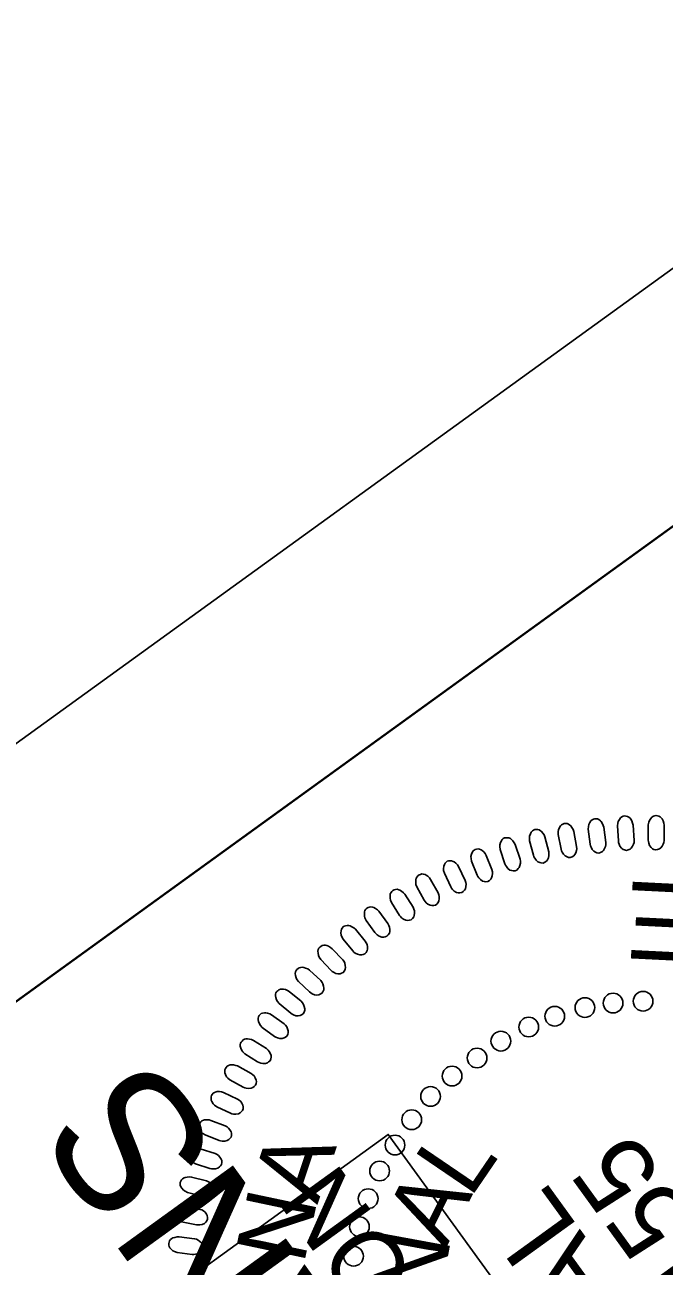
# Model space of a CAD drawing. Extents: x 474248 to 476123, y 501895 to 503900.
# Drawn here: x 474338.6 to 474390.5, y 503280.5 to 503381.5 of the extents above; entities that cross this region are included whole.
import ezdxf

# ---------------------------------------------------------------- set-up
doc = ezdxf.new("R2010")
doc.units = 0
for name, color, linetype in [('Sheet PE Seal Cell', 7, 'Continuous'), ('Sheet Plan CELL', 7, 'Continuous'), ('Sheet Plot Border Outside CELL', 7, 'Continuous'), ('Sheet Sticker Incomplete CELL', 7, 'Continuous')]:
    doc.layers.add(name, color=color, linetype=linetype)

msp = doc.modelspace()

# ---------------------------------------------------------------- linework, layer by layer
at = {"layer": 'Sheet PE Seal Cell'}
for points in [[(474382.16, 503314.41), (474381.94, 503315.62), (474381.93, 503315.84), (474381.96, 503315.99), (474382.04, 503316.17), (474382.11, 503316.3), (474382.21, 503316.4), (474382.3, 503316.46), (474382.41, 503316.5), (474382.52, 503316.5), (474382.65, 503316.49), (474382.76, 503316.45), (474382.88, 503316.37), (474382.96, 503316.31), (474383.05, 503316.17), (474383.14, 503316.01), (474383.19, 503315.85), (474383.43, 503314.62), (474383.44, 503314.45), (474383.42, 503314.3), (474383.37, 503314.13), (474383.28, 503313.97), (474383.2, 503313.88), (474383.06, 503313.79), (474382.91, 503313.74), (474382.76, 503313.75), (474382.65, 503313.78), (474382.5, 503313.86), (474382.36, 503314), (474382.26, 503314.16), (474382.2, 503314.29)], [(474384.52, 503314.82), (474384.37, 503316.04), (474384.38, 503316.26), (474384.41, 503316.41), (474384.5, 503316.59), (474384.59, 503316.71), (474384.69, 503316.8), (474384.79, 503316.85), (474384.9, 503316.89), (474385.01, 503316.88), (474385.13, 503316.87), (474385.24, 503316.82), (474385.36, 503316.73), (474385.43, 503316.66), (474385.51, 503316.52), (474385.59, 503316.35), (474385.64, 503316.2), (474385.8, 503314.95), (474385.8, 503314.78), (474385.77, 503314.63), (474385.7, 503314.47), (474385.61, 503314.31), (474385.52, 503314.22), (474385.37, 503314.14), (474385.23, 503314.1), (474385.07, 503314.13), (474384.96, 503314.16), (474384.82, 503314.25), (474384.69, 503314.4), (474384.6, 503314.57), (474384.55, 503314.69)], [(474386.82, 503315.08), (474386.74, 503316.3), (474386.77, 503316.53), (474386.81, 503316.67), (474386.91, 503316.84), (474387, 503316.96), (474387.11, 503317.05), (474387.21, 503317.09), (474387.32, 503317.12), (474387.43, 503317.11), (474387.55, 503317.08), (474387.66, 503317.03), (474387.77, 503316.94), (474387.84, 503316.86), (474387.91, 503316.71), (474387.98, 503316.54), (474388.02, 503316.38), (474388.1, 503315.13), (474388.09, 503314.96), (474388.05, 503314.82), (474387.97, 503314.65), (474387.87, 503314.5), (474387.78, 503314.42), (474387.62, 503314.35), (474387.48, 503314.32), (474387.32, 503314.35), (474387.22, 503314.39), (474387.08, 503314.49), (474386.95, 503314.65), (474386.88, 503314.82), (474386.84, 503314.95)], [(474389.25, 503315.16), (474389.25, 503316.39), (474389.29, 503316.61), (474389.34, 503316.75), (474389.45, 503316.91), (474389.55, 503317.02), (474389.66, 503317.1), (474389.77, 503317.14), (474389.88, 503317.16), (474389.99, 503317.14), (474390.11, 503317.11), (474390.21, 503317.05), (474390.32, 503316.95), (474390.38, 503316.87), (474390.45, 503316.72), (474390.5, 503316.54), (474390.53, 503316.38), (474390.53, 503315.13), (474390.51, 503314.96), (474390.46, 503314.82), (474390.37, 503314.66), (474390.26, 503314.52), (474390.16, 503314.44), (474390.01, 503314.38), (474389.86, 503314.36), (474389.71, 503314.4), (474389.6, 503314.45), (474389.48, 503314.55), (474389.36, 503314.72), (474389.29, 503314.9), (474389.26, 503315.03)], [(474377.59, 503313.23), (474377.22, 503314.4), (474377.19, 503314.62), (474377.19, 503314.77), (474377.25, 503314.96), (474377.31, 503315.1), (474377.39, 503315.21), (474377.47, 503315.28), (474377.58, 503315.33), (474377.69, 503315.34), (474377.81, 503315.35), (474377.93, 503315.33), (474378.06, 503315.27), (474378.14, 503315.21), (474378.25, 503315.09), (474378.36, 503314.93), (474378.43, 503314.79), (474378.83, 503313.6), (474378.86, 503313.43), (474378.86, 503313.28), (474378.82, 503313.1), (474378.76, 503312.93), (474378.69, 503312.83), (474378.56, 503312.72), (474378.42, 503312.66), (474378.27, 503312.65), (474378.15, 503312.67), (474378, 503312.72), (474377.84, 503312.85), (474377.72, 503313), (474377.65, 503313.11)], [(474379.91, 503313.92), (474379.61, 503315.1), (474379.59, 503315.33), (474379.6, 503315.47), (474379.67, 503315.67), (474379.74, 503315.8), (474379.83, 503315.9), (474379.92, 503315.97), (474380.02, 503316.01), (474380.14, 503316.02), (474380.26, 503316.02), (474380.38, 503315.99), (474380.5, 503315.92), (474380.58, 503315.86), (474380.68, 503315.73), (474380.78, 503315.57), (474380.84, 503315.42), (474381.16, 503314.2), (474381.18, 503314.03), (474381.17, 503313.89), (474381.13, 503313.71), (474381.05, 503313.55), (474380.98, 503313.45), (474380.84, 503313.35), (474380.7, 503313.29), (474380.54, 503313.3), (474380.43, 503313.32), (474380.28, 503313.38), (474380.13, 503313.52), (474380.02, 503313.68), (474379.96, 503313.79)], [(474375.34, 503312.3), (474374.89, 503313.45), (474374.85, 503313.66), (474374.84, 503313.81), (474374.89, 503314.01), (474374.94, 503314.15), (474375.01, 503314.27), (474375.09, 503314.34), (474375.19, 503314.4), (474375.3, 503314.42), (474375.43, 503314.44), (474375.54, 503314.42), (474375.68, 503314.37), (474375.76, 503314.31), (474375.88, 503314.2), (474376, 503314.05), (474376.08, 503313.91), (474376.55, 503312.75), (474376.59, 503312.58), (474376.6, 503312.44), (474376.57, 503312.25), (474376.52, 503312.08), (474376.46, 503311.97), (474376.34, 503311.86), (474376.2, 503311.79), (474376.05, 503311.77), (474375.93, 503311.78), (474375.78, 503311.82), (474375.61, 503311.94), (474375.48, 503312.08), (474375.4, 503312.19)], [(474373.2, 503311.35), (474372.68, 503312.46), (474372.62, 503312.67), (474372.6, 503312.82), (474372.63, 503313.02), (474372.68, 503313.16), (474372.74, 503313.28), (474372.82, 503313.36), (474372.92, 503313.43), (474373.02, 503313.46), (474373.15, 503313.48), (474373.27, 503313.47), (474373.4, 503313.42), (474373.49, 503313.38), (474373.62, 503313.27), (474373.75, 503313.13), (474373.83, 503313), (474374.37, 503311.86), (474374.42, 503311.7), (474374.44, 503311.56), (474374.43, 503311.37), (474374.39, 503311.2), (474374.33, 503311.09), (474374.22, 503310.97), (474374.09, 503310.88), (474373.94, 503310.86), (474373.82, 503310.86), (474373.66, 503310.89), (474373.48, 503311), (474373.35, 503311.13), (474373.27, 503311.24)], [(474371.03, 503310.27), (474370.44, 503311.34), (474370.37, 503311.55), (474370.35, 503311.7), (474370.36, 503311.91), (474370.4, 503312.05), (474370.46, 503312.17), (474370.53, 503312.26), (474370.62, 503312.33), (474370.73, 503312.36), (474370.85, 503312.4), (474370.97, 503312.39), (474371.11, 503312.36), (474371.2, 503312.31), (474371.33, 503312.22), (474371.47, 503312.09), (474371.56, 503311.96), (474372.17, 503310.86), (474372.23, 503310.7), (474372.26, 503310.56), (474372.26, 503310.37), (474372.23, 503310.2), (474372.18, 503310.08), (474372.07, 503309.95), (474371.95, 503309.86), (474371.8, 503309.83), (474371.68, 503309.82), (474371.52, 503309.85), (474371.34, 503309.94), (474371.19, 503310.06), (474371.11, 503310.16)], [(474369.04, 503309.03), (474368.38, 503310.07), (474368.3, 503310.27), (474368.27, 503310.42), (474368.27, 503310.62), (474368.29, 503310.77), (474368.35, 503310.89), (474368.41, 503310.98), (474368.5, 503311.06), (474368.6, 503311.1), (474368.72, 503311.14), (474368.84, 503311.15), (474368.98, 503311.12), (474369.07, 503311.08), (474369.21, 503310.99), (474369.36, 503310.87), (474369.46, 503310.75), (474370.14, 503309.69), (474370.21, 503309.54), (474370.25, 503309.39), (474370.26, 503309.21), (474370.24, 503309.03), (474370.2, 503308.91), (474370.1, 503308.78), (474369.98, 503308.68), (474369.83, 503308.64), (474369.72, 503308.62), (474369.56, 503308.64), (474369.37, 503308.72), (474369.21, 503308.84), (474369.12, 503308.93)], [(474367.04, 503307.63), (474366.32, 503308.62), (474366.22, 503308.82), (474366.18, 503308.96), (474366.18, 503309.17), (474366.19, 503309.31), (474366.23, 503309.44), (474366.3, 503309.54), (474366.37, 503309.62), (474366.48, 503309.67), (474366.59, 503309.71), (474366.71, 503309.73), (474366.85, 503309.71), (474366.95, 503309.68), (474367.09, 503309.6), (474367.25, 503309.49), (474367.36, 503309.37), (474368.1, 503308.36), (474368.18, 503308.21), (474368.23, 503308.07), (474368.25, 503307.88), (474368.24, 503307.71), (474368.21, 503307.58), (474368.11, 503307.44), (474368, 503307.34), (474367.86, 503307.28), (474367.75, 503307.26), (474367.59, 503307.27), (474367.39, 503307.34), (474367.23, 503307.44), (474367.13, 503307.53)], [(474365.24, 503306.14), (474364.46, 503307.09), (474364.35, 503307.28), (474364.3, 503307.42), (474364.28, 503307.62), (474364.29, 503307.77), (474364.32, 503307.9), (474364.38, 503308), (474364.45, 503308.09), (474364.55, 503308.14), (474364.66, 503308.19), (474364.78, 503308.21), (474364.92, 503308.2), (474365.02, 503308.18), (474365.17, 503308.11), (474365.33, 503308.01), (474365.45, 503307.9), (474366.25, 503306.93), (474366.34, 503306.79), (474366.4, 503306.65), (474366.43, 503306.47), (474366.43, 503306.29), (474366.41, 503306.17), (474366.32, 503306.02), (474366.22, 503305.91), (474366.08, 503305.85), (474365.97, 503305.82), (474365.81, 503305.82), (474365.61, 503305.87), (474365.44, 503305.97), (474365.33, 503306.05)], [(474363.47, 503304.55), (474362.63, 503305.45), (474362.51, 503305.64), (474362.45, 503305.77), (474362.42, 503305.97), (474362.41, 503306.12), (474362.44, 503306.26), (474362.49, 503306.36), (474362.56, 503306.45), (474362.65, 503306.51), (474362.76, 503306.57), (474362.88, 503306.6), (474363.02, 503306.6), (474363.12, 503306.58), (474363.27, 503306.52), (474363.44, 503306.43), (474363.56, 503306.32), (474364.43, 503305.41), (474364.53, 503305.27), (474364.59, 503305.14), (474364.63, 503304.96), (474364.65, 503304.78), (474364.63, 503304.66), (474364.56, 503304.51), (474364.46, 503304.39), (474364.32, 503304.32), (474364.21, 503304.28), (474364.05, 503304.27), (474363.85, 503304.31), (474363.68, 503304.4), (474363.57, 503304.47)], [(474361.73, 503302.8), (474360.83, 503303.64), (474360.7, 503303.82), (474360.63, 503303.95), (474360.59, 503304.15), (474360.57, 503304.3), (474360.59, 503304.44), (474360.64, 503304.54), (474360.7, 503304.63), (474360.79, 503304.7), (474360.89, 503304.77), (474361.01, 503304.8), (474361.15, 503304.81), (474361.25, 503304.8), (474361.41, 503304.75), (474361.58, 503304.67), (474361.71, 503304.57), (474362.63, 503303.72), (474362.74, 503303.58), (474362.81, 503303.46), (474362.86, 503303.28), (474362.89, 503303.1), (474362.88, 503302.98), (474362.81, 503302.82), (474362.73, 503302.7), (474362.6, 503302.62), (474362.49, 503302.58), (474362.33, 503302.55), (474362.12, 503302.58), (474361.94, 503302.66), (474361.83, 503302.72)], [(474360.2, 503301.07), (474359.26, 503301.85), (474359.11, 503302.02), (474359.04, 503302.15), (474358.98, 503302.34), (474358.95, 503302.49), (474358.97, 503302.63), (474359, 503302.73), (474359.06, 503302.83), (474359.14, 503302.9), (474359.24, 503302.98), (474359.36, 503303.02), (474359.5, 503303.04), (474359.6, 503303.03), (474359.76, 503302.99), (474359.94, 503302.92), (474360.07, 503302.83), (474361.04, 503302.04), (474361.16, 503301.91), (474361.24, 503301.79), (474361.3, 503301.62), (474361.34, 503301.44), (474361.34, 503301.32), (474361.28, 503301.16), (474361.2, 503301.03), (474361.08, 503300.94), (474360.97, 503300.89), (474360.81, 503300.86), (474360.61, 503300.87), (474360.43, 503300.94), (474360.31, 503301)], [(474358.88, 503299.19), (474357.88, 503299.91), (474357.73, 503300.07), (474357.65, 503300.2), (474357.58, 503300.39), (474357.54, 503300.53), (474357.55, 503300.67), (474357.58, 503300.78), (474357.63, 503300.88), (474357.71, 503300.96), (474357.8, 503301.04), (474357.91, 503301.09), (474358.06, 503301.11), (474358.15, 503301.11), (474358.32, 503301.08), (474358.5, 503301.02), (474358.64, 503300.95), (474359.66, 503300.21), (474359.78, 503300.09), (474359.87, 503299.97), (474359.94, 503299.81), (474359.99, 503299.64), (474360, 503299.51), (474359.95, 503299.35), (474359.88, 503299.21), (474359.76, 503299.12), (474359.66, 503299.06), (474359.5, 503299.02), (474359.3, 503299.02), (474359.11, 503299.07), (474358.99, 503299.13)], [(474357.51, 503297.12), (474356.48, 503297.78), (474356.31, 503297.93), (474356.22, 503298.05), (474356.14, 503298.24), (474356.1, 503298.38), (474356.09, 503298.52), (474356.12, 503298.63), (474356.16, 503298.73), (474356.24, 503298.81), (474356.33, 503298.9), (474356.43, 503298.96), (474356.57, 503298.99), (474356.67, 503299), (474356.84, 503298.97), (474357.02, 503298.93), (474357.17, 503298.86), (474358.23, 503298.19), (474358.36, 503298.08), (474358.45, 503297.97), (474358.54, 503297.81), (474358.6, 503297.64), (474358.61, 503297.51), (474358.58, 503297.35), (474358.52, 503297.21), (474358.4, 503297.11), (474358.3, 503297.05), (474358.15, 503296.99), (474357.94, 503296.98), (474357.76, 503297.02), (474357.63, 503297.07)], [(474356.34, 503295.06), (474355.26, 503295.66), (474355.09, 503295.8), (474354.99, 503295.91), (474354.9, 503296.09), (474354.85, 503296.23), (474354.83, 503296.36), (474354.85, 503296.47), (474354.89, 503296.58), (474354.96, 503296.67), (474355.04, 503296.76), (474355.14, 503296.82), (474355.28, 503296.87), (474355.38, 503296.88), (474355.55, 503296.87), (474355.73, 503296.83), (474355.88, 503296.78), (474356.99, 503296.17), (474357.12, 503296.07), (474357.22, 503295.97), (474357.32, 503295.81), (474357.39, 503295.64), (474357.41, 503295.52), (474357.39, 503295.35), (474357.33, 503295.21), (474357.22, 503295.1), (474357.13, 503295.04), (474356.98, 503294.97), (474356.78, 503294.95), (474356.59, 503294.98), (474356.46, 503295.01)], [(474355.3, 503292.95), (474354.19, 503293.47), (474354.01, 503293.6), (474353.9, 503293.7), (474353.8, 503293.88), (474353.74, 503294.01), (474353.72, 503294.15), (474353.73, 503294.26), (474353.76, 503294.37), (474353.82, 503294.46), (474353.9, 503294.56), (474354, 503294.63), (474354.13, 503294.68), (474354.23, 503294.7), (474354.4, 503294.7), (474354.58, 503294.67), (474354.74, 503294.63), (474355.88, 503294.09), (474356.02, 503294), (474356.13, 503293.9), (474356.23, 503293.75), (474356.31, 503293.59), (474356.34, 503293.47), (474356.33, 503293.3), (474356.28, 503293.16), (474356.18, 503293.04), (474356.09, 503292.97), (474355.95, 503292.89), (474355.74, 503292.86), (474355.55, 503292.87), (474355.42, 503292.9)], [(474354.38, 503290.72), (474353.24, 503291.18), (474353.05, 503291.29), (474352.94, 503291.39), (474352.82, 503291.56), (474352.76, 503291.69), (474352.72, 503291.82), (474352.73, 503291.94), (474352.75, 503292.05), (474352.81, 503292.14), (474352.88, 503292.24), (474352.97, 503292.32), (474353.11, 503292.38), (474353.2, 503292.4), (474353.37, 503292.41), (474353.56, 503292.4), (474353.71, 503292.36), (474354.88, 503291.91), (474355.03, 503291.82), (474355.14, 503291.73), (474355.26, 503291.59), (474355.35, 503291.43), (474355.39, 503291.31), (474355.38, 503291.14), (474355.35, 503291), (474355.25, 503290.87), (474355.17, 503290.79), (474355.03, 503290.71), (474354.83, 503290.66), (474354.64, 503290.67), (474354.5, 503290.69)], [(474353.62, 503288.45), (474352.46, 503288.83), (474352.26, 503288.93), (474352.14, 503289.02), (474352.02, 503289.18), (474351.94, 503289.31), (474351.9, 503289.44), (474351.9, 503289.55), (474351.91, 503289.67), (474351.97, 503289.77), (474352.03, 503289.87), (474352.12, 503289.95), (474352.25, 503290.02), (474352.34, 503290.05), (474352.51, 503290.07), (474352.7, 503290.07), (474352.85, 503290.04), (474354.05, 503289.66), (474354.21, 503289.58), (474354.32, 503289.5), (474354.45, 503289.36), (474354.55, 503289.21), (474354.59, 503289.1), (474354.6, 503288.93), (474354.57, 503288.78), (474354.49, 503288.65), (474354.41, 503288.57), (474354.27, 503288.48), (474354.08, 503288.42), (474353.88, 503288.41), (474353.75, 503288.42)], [(474353, 503286.19), (474351.82, 503286.5), (474351.61, 503286.59), (474351.49, 503286.68), (474351.35, 503286.83), (474351.27, 503286.95), (474351.22, 503287.08), (474351.21, 503287.19), (474351.22, 503287.31), (474351.27, 503287.41), (474351.33, 503287.52), (474351.41, 503287.6), (474351.53, 503287.68), (474351.63, 503287.72), (474351.79, 503287.74), (474351.98, 503287.76), (474352.14, 503287.74), (474353.35, 503287.43), (474353.51, 503287.37), (474353.64, 503287.29), (474353.77, 503287.16), (474353.88, 503287.02), (474353.93, 503286.9), (474353.95, 503286.74), (474353.93, 503286.59), (474353.85, 503286.45), (474353.78, 503286.36), (474353.65, 503286.27), (474353.46, 503286.19), (474353.27, 503286.17), (474353.13, 503286.18)], [(474352.53, 503283.86), (474351.33, 503284.1), (474351.12, 503284.18), (474350.99, 503284.25), (474350.85, 503284.39), (474350.76, 503284.51), (474350.7, 503284.64), (474350.68, 503284.75), (474350.68, 503284.86), (474350.73, 503284.97), (474350.78, 503285.08), (474350.86, 503285.17), (474350.97, 503285.25), (474351.06, 503285.3), (474351.22, 503285.34), (474351.41, 503285.36), (474351.57, 503285.35), (474352.81, 503285.12), (474352.97, 503285.07), (474353.1, 503285), (474353.24, 503284.88), (474353.35, 503284.74), (474353.41, 503284.63), (474353.44, 503284.47), (474353.43, 503284.31), (474353.37, 503284.18), (474353.3, 503284.08), (474353.18, 503283.98), (474352.99, 503283.89), (474352.8, 503283.86), (474352.66, 503283.85)], [(474352.19, 503281.46), (474350.97, 503281.61), (474350.76, 503281.68), (474350.62, 503281.75), (474350.47, 503281.88), (474350.37, 503281.99), (474350.31, 503282.11), (474350.28, 503282.22), (474350.28, 503282.34), (474350.31, 503282.45), (474350.36, 503282.56), (474350.43, 503282.66), (474350.54, 503282.75), (474350.63, 503282.8), (474350.78, 503282.84), (474350.97, 503282.88), (474351.13, 503282.88), (474352.38, 503282.73), (474352.54, 503282.69), (474352.68, 503282.62), (474352.82, 503282.51), (474352.95, 503282.39), (474353.01, 503282.28), (474353.05, 503282.12), (474353.05, 503281.96), (474353, 503281.82), (474352.93, 503281.72), (474352.82, 503281.61), (474352.63, 503281.51), (474352.45, 503281.47), (474352.32, 503281.46)]]:
    msp.add_lwpolyline(points, close=True, dxfattribs=at)
for centre in [(474384.1, 503301.53), (474386.39, 503301.9), (474388.83, 503302.05), (474381.65, 503300.83), (474379.54, 503299.95), (474377.27, 503298.8), (474375.34, 503297.43), (474373.31, 503295.96), (474371.56, 503294.3), (474370.03, 503292.41), (474368.67, 503290.35), (474367.42, 503288.24), (474366.49, 503285.99), (474365.78, 503283.71), (474365.3, 503281.31)]:
    msp.add_circle(centre, 0.801, dxfattribs=at)
at = {"layer": 'Sheet Plan CELL'}
for points in [[(474276.58, 503257.68), (475156.32, 502042.7), (476006.78, 502658.5), (475127.06, 503873.46)], [(474365.67, 503198.69), (474307.02, 503279.67), (474398.14, 503345.66), (474456.8, 503264.68)]]:
    msp.add_lwpolyline(points, close=True, dxfattribs=at)
at = {"layer": 'Sheet Plot Border Outside CELL'}
msp.add_lwpolyline([(475235.74, 501894.66), (474248.41, 503258.24), (475135.32, 503900.43), (476122.66, 502536.85)], close=True, dxfattribs=at)
at = {"layer": 'Sheet Sticker Incomplete CELL'}
msp.add_lwpolyline([(474454.33, 503172.15), (474435.3, 503158.36), (474349.09, 503277.43), (474368.12, 503291.21)], close=True, dxfattribs=at)

# ---------------------------------------------------------------- texts
at = {"layer": 'Sheet PE Seal Cell'}
for s, height, rotation, p in [('E', 6.24, 177.1721, (474393.18, 503311.51)), ('A', 5.67, 71.5767, (474362.36, 503285.46)), ('L', 5.67, 55.7347, (474374.77, 503285.94)), ('46155', 6.236, 125.8852, (474401.37, 503272.89)), ('A', 5.67, 63.6745, (474372.78, 503281.88)), ('SEAL', 6.236, 125.8852, (474393.45, 503270.05)), ('N', 5.67, 78.066, (474361.25, 503280.55)), ('N', 5.67, 79.5541, (474372.25, 503277.37))]:
    msp.add_text(s, height=height, rotation=rotation, dxfattribs=at).set_placement(p)
at = {"layer": 'Sheet Sticker Incomplete CELL'}
for s, height, p in [('INCOMPLETE PLANS', 11.52, (474439.61, 503172.53)), ('DO NOT USE FOR R/W ACQUISITION', 5.76, (474443.33, 503179.24))]:
    msp.add_text(s, height=height, rotation=125.9074, dxfattribs=at).set_placement(p)

doc.saveas('drawing.dxf')
